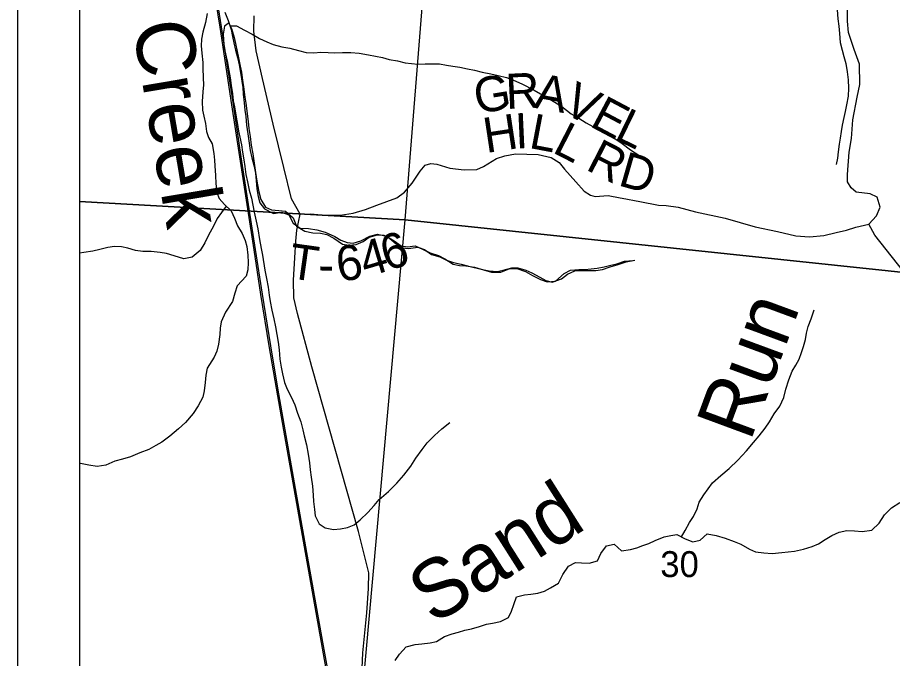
# Model space of a CAD drawing. Extents: x 0 to 40.8, y 0 to 22.
# Drawn here: x 2 to 3.414, y 18.699 to 19.735 of the extents above; entities that cross this region are included whole.
import ezdxf

# ---------------------------------------------------------------- set-up
doc = ezdxf.new("R2010")
doc.units = 0
for name, color, linetype in [('Default', 7, 'Continuous'), ('GM_X_County_Road', 7, 'Continuous'), ('GM_X_Minor_River', 7, 'Continuous'), ('GM_X_Minor_River_Text', 7, 'Continuous'), ('GM_X_Rail_Line', 7, 'Continuous'), ('GM_X_Section', 7, 'Continuous'), ('GM_X_Section_Text', 7, 'Continuous'), ('GM_X_Township_Road', 7, 'Continuous'), ('GM_X_Township_Road_Text', 7, 'Continuous'), ('SH_Cut_Line', 7, 'Continuous'), ('SH_Data', 7, 'Continuous')]:
    doc.layers.add(name, color=color, linetype=linetype)

msp = doc.modelspace()

# ---------------------------------------------------------------- linework, layer by layer
at = {"layer": 'Default'}
msp.add_lwpolyline([(3.6829, 20.9), (2.1, 20.9), (2.1, 17.4153), (2.4594, 17.3966), (2.8463, 17.3693), (2.8484, 17.3691), (3.1244, 17.3534), (3.4481, 17.3334), (3.5638, 19.132), (3.5742, 19.2945), (3.575, 19.3064), (3.6386, 20.2396), (3.6672, 20.5588), (3.6703, 20.6733)], close=True, dxfattribs=at)
at = {"layer": 'GM_X_County_Road'}
for points in [[(2.1, 20.4303), (2.1, 19.4381), (2.6264, 19.4085), (2.7045, 20.3832)], [(2.1, 19.4381), (2.1, 18.4259), (2.5343, 18.3862), (2.6264, 19.4085)]]:
    msp.add_lwpolyline(points, close=True, dxfattribs=at)
for points in [[(3.4403, 19.3142), (3.3856, 19.3835), (3.3759, 19.4012), (3.3878, 19.415), (3.3937, 19.429), (3.389, 19.4448), (3.3777, 19.4501), (3.355, 19.4532), (3.347, 19.4598), (3.341, 19.4698), (3.341, 19.4818), (3.344, 19.5176), (3.3476, 19.5399), (3.3496, 19.5699), (3.357, 19.6065), (3.3613, 19.6269), (3.3605, 19.6598), (3.3517, 19.6838), (3.3429, 19.7111), (3.341, 19.7294), (3.3414, 19.7557)], [(2.5547, 18.6345), (2.5581, 18.7086), (2.5645, 18.7732), (2.5674, 18.8123), (2.5679, 18.8378), (2.5508, 18.9044), (2.4758, 19.1705), (2.4527, 19.2569), (2.4464, 19.2824), (2.4458, 19.3109), (2.4482, 19.3466), (2.4499, 19.374), (2.4511, 19.3918), (2.457, 19.4172), (2.443, 19.442), (2.4304, 19.4926), (2.4129, 19.5631), (2.3958, 19.6365), (2.3858, 19.6814), (2.3818, 19.713), (2.3826, 19.7381)]]:
    msp.add_lwpolyline(points, dxfattribs=at)
at = {"layer": 'GM_X_Minor_River'}
for points in [[(2.3063, 19.7416), (2.3038, 19.7272), (2.2993, 19.7118), (2.2972, 19.7004), (2.297, 19.6894), (2.2979, 19.6776), (2.2995, 19.6628), (2.2997, 19.6533), (2.3002, 19.6377), (2.3003, 19.6264), (2.2997, 19.6154), (2.2983, 19.5998), (2.2991, 19.5854), (2.3012, 19.5759), (2.304, 19.564), (2.3053, 19.5511), (2.3085, 19.5415), (2.3144, 19.5312), (2.3175, 19.5156), (2.3184, 19.5049), (2.319, 19.4954), (2.3199, 19.4798), (2.3204, 19.4669), (2.322, 19.4525), (2.3256, 19.4429), (2.3345, 19.4332), (2.3453, 19.4228), (2.3508, 19.4109), (2.3554, 19.3987), (2.3628, 19.386), (2.3679, 19.3749), (2.3704, 19.3653), (2.3724, 19.3513), (2.3729, 19.3391), (2.3723, 19.3277), (2.3694, 19.3175), (2.3551, 19.3015), (2.3511, 19.2898), (2.3474, 19.2762), (2.3361, 19.259), (2.3289, 19.2432), (2.3276, 19.233), (2.327, 19.2227), (2.3248, 19.2072), (2.322, 19.1959), (2.3176, 19.1861), (2.3067, 19.1688), (2.3045, 19.1571), (2.3032, 19.1454), (2.3014, 19.1321), (2.2993, 19.1219), (2.2918, 19.1076), (2.284, 19.0953), (2.2712, 19.0807), (2.2604, 19.0707), (2.2461, 19.0584), (2.2331, 19.0488), (2.2235, 19.0433), (2.212, 19.0371), (2.1978, 19.0317), (2.1826, 19.0252), (2.1696, 19.0212), (2.1574, 19.0184), (2.1429, 19.0119), (2.1288, 19.0095), (2.1152, 19.0117), (2.102, 19.0142), (2.1, 19.0143)], [(2.3352, 19.7441), (2.3406, 19.7303), (2.3453, 19.7158), (2.3473, 19.7048), (2.3498, 19.6945), (2.3522, 19.6826), (2.3554, 19.6704), (2.3582, 19.6586), (2.3609, 19.6434), (2.3626, 19.6323), (2.3639, 19.6224), (2.3649, 19.6114), (2.3665, 19.5973), (2.3674, 19.5856), (2.3687, 19.5753), (2.37, 19.5612), (2.372, 19.5475), (2.3736, 19.5357), (2.376, 19.5205), (2.3788, 19.5083), (2.3823, 19.4945), (2.3848, 19.4835), (2.3857, 19.4717), (2.3869, 19.4584), (2.389, 19.4458), (2.3918, 19.4359), (2.3992, 19.4263)], [(3.3245, 19.7477), (3.3257, 19.7329), (3.3274, 19.7215), (3.3283, 19.7097), (3.3291, 19.6949), (3.3323, 19.6827), (3.3355, 19.672), (3.3383, 19.6609), (3.3404, 19.6476), (3.3424, 19.6346), (3.3429, 19.621), (3.3423, 19.6084), (3.3397, 19.5941), (3.3372, 19.5835), (3.3351, 19.5737), (3.3326, 19.5612), (3.3309, 19.551), (3.3292, 19.5404), (3.3279, 19.5305), (3.3261, 19.5181), (3.3248, 19.5078), (3.3227, 19.4976)], [(2.3418, 19.7265), (2.3344, 19.7213), (2.3322, 19.7085), (2.3328, 19.699), (2.3341, 19.6864), (2.3372, 19.6719), (2.3393, 19.6624), (2.3417, 19.6494), (2.3438, 19.638), (2.3454, 19.6255), (2.3474, 19.6121), (2.3487, 19.6007), (2.3504, 19.5908), (2.3535, 19.5741), (2.3556, 19.5626), (2.3573, 19.5516), (2.359, 19.5421), (2.3618, 19.5295), (2.3638, 19.5177), (2.3655, 19.5055), (2.3675, 19.4945), (2.3692, 19.4815), (2.3716, 19.4697), (2.3744, 19.4564), (2.3779, 19.4434), (2.3804, 19.432), (2.3824, 19.4209), (2.3855, 19.406), (2.3883, 19.3935), (2.391, 19.3763), (2.3938, 19.3618), (2.3959, 19.3512), (2.3999, 19.3268), (2.4023, 19.3135), (2.4051, 19.2994), (2.4067, 19.2864), (2.4081, 19.2762), (2.4112, 19.2621), (2.414, 19.2483), (2.4171, 19.2354), (2.4192, 19.2228), (2.4212, 19.2106), (2.4229, 19.1981), (2.4241, 19.1829), (2.4261, 19.1703), (2.4282, 19.1596), (2.4317, 19.1455), (2.436, 19.1348), (2.443, 19.121), (2.4484, 19.1091), (2.4527, 19.0957), (2.4578, 19.0816), (2.4609, 19.0686), (2.463, 19.0591), (2.4669, 19.0446), (2.4697, 19.0294), (2.4717, 19.0153), (2.473, 19.0042), (2.4746, 18.9921), (2.4766, 18.978), (2.4779, 18.9635), (2.4784, 18.9529), (2.4797, 18.94), (2.481, 18.9297), (2.4876, 18.9167), (2.4973, 18.9104), (2.5105, 18.9079), (2.5219, 18.9091), (2.533, 18.9112), (2.544, 18.9152), (2.5537, 18.9233), (2.566, 18.9352), (2.5761, 18.9464), (2.5843, 18.9561), (2.5993, 18.9691), (2.6132, 18.9829), (2.6245, 18.9956), (2.6357, 19.0101), (2.6436, 19.0233), (2.6537, 19.0371), (2.6622, 19.0476), (2.6738, 19.0599), (2.6854, 19.0703), (2.6985, 19.0806)], [(2.3432, 19.7222), (2.346, 19.7173), (2.3499, 19.7028), (2.3524, 19.6933), (2.3548, 19.6803), (2.3573, 19.67), (2.36, 19.6567), (2.3617, 19.6468), (2.3638, 19.6342), (2.3658, 19.6194), (2.3674, 19.6064), (2.3687, 19.5969), (2.3727, 19.5672), (2.374, 19.5558), (2.3757, 19.5429), (2.3777, 19.5288), (2.3804, 19.5151), (2.3821, 19.5037), (2.3841, 19.4888), (2.3858, 19.4778), (2.3878, 19.4648), (2.3899, 19.4538), (2.393, 19.4412), (2.4008, 19.4285), (2.4105, 19.4245), (2.4223, 19.4235), (2.4332, 19.4222), (2.4452, 19.4117), (2.451, 19.3983), (2.4641, 19.3901), (2.4773, 19.3875), (2.4898, 19.3865), (2.5, 19.3848), (2.5109, 19.3785), (2.5251, 19.3687), (2.5353, 19.3674), (2.5475, 19.3683), (2.5586, 19.373), (2.5682, 19.3804), (2.5815, 19.384), (2.5918, 19.3837), (2.6015, 19.3782), (2.6119, 19.3693), (2.6221, 19.363), (2.6319, 19.3621), (2.6467, 19.3641), (2.6576, 19.3601), (2.6692, 19.3522), (2.6824, 19.3486), (2.693, 19.343), (2.7043, 19.3394), (2.7171, 19.3365), (2.7273, 19.334), (2.7514, 19.3282), (2.7624, 19.3261), (2.7753, 19.3247), (2.7848, 19.3268), (2.7989, 19.3307), (2.8087, 19.3305), (2.8212, 19.3268), (2.8313, 19.3225), (2.8441, 19.3154), (2.8538, 19.3103), (2.8637, 19.3078), (2.8789, 19.3128), (2.8885, 19.3206), (2.9008, 19.326), (2.9103, 19.3266), (2.9243, 19.3263), (2.9345, 19.3265), (2.9452, 19.3278), (2.9578, 19.3321), (2.9707, 19.336), (2.9837, 19.3403), (2.9974, 19.3431)], [(2.3434, 19.7217), (2.3537, 19.7217), (2.3669, 19.715), (2.3792, 19.7083), (2.3912, 19.7016), (2.4029, 19.6961), (2.413, 19.6917), (2.427, 19.688), (2.4402, 19.6858), (2.4542, 19.6818), (2.4666, 19.6785), (2.4791, 19.6782), (2.4902, 19.6795), (2.5019, 19.6786), (2.5121, 19.6783), (2.5254, 19.6788), (2.5387, 19.6786), (2.5519, 19.6776), (2.567, 19.675), (2.5897, 19.6707), (2.6006, 19.6675), (2.6139, 19.665), (2.6263, 19.6621), (2.6369, 19.6611), (2.6471, 19.6601), (2.6589, 19.6603), (2.6718, 19.6604), (2.682, 19.6602), (2.693, 19.6581), (2.7032, 19.6567), (2.7149, 19.655), (2.727, 19.6521), (2.7383, 19.65), (2.7508, 19.6467), (2.7647, 19.6441), (2.7768, 19.6416), (2.79, 19.6383), (2.8013, 19.6339), (2.8152, 19.628), (2.8348, 19.6177), (2.8453, 19.6118), (2.8576, 19.6047), (2.8685, 19.5984), (2.8794, 19.5914), (2.8947, 19.5797), (2.9071, 19.5726), (2.9187, 19.5652), (2.9296, 19.5593), (2.9431, 19.5522), (2.9547, 19.5463), (2.9644, 19.5404), (2.9772, 19.5318), (2.9906, 19.5216), (3.0041, 19.5126)], [(2.3372, 19.4306), (2.3297, 19.4204), (2.3227, 19.4103), (2.316, 19.3968), (2.3093, 19.3848), (2.3026, 19.3709), (2.2951, 19.3585), (2.282, 19.3477), (2.2687, 19.3453), (2.2533, 19.3502), (2.2408, 19.3539), (2.2303, 19.3556), (2.2159, 19.357), (2.2026, 19.3573), (2.1909, 19.3586), (2.1781, 19.3623), (2.1679, 19.3648), (2.1565, 19.365), (2.1459, 19.3637), (2.1333, 19.3605), (2.1219, 19.3577), (2.1074, 19.3553), (2.1, 19.3546)], [(2.3992, 19.4263), (2.4135, 19.4184), (2.4264, 19.4208), (2.4384, 19.4164), (2.4454, 19.403), (2.457, 19.3948), (2.4702, 19.3941), (2.4835, 19.3923), (2.4974, 19.3886), (2.5125, 19.3811), (2.5222, 19.3756), (2.5327, 19.3716), (2.5426, 19.3707), (2.5548, 19.3742), (2.5693, 19.3819), (2.5819, 19.3851), (2.5963, 19.3821), (2.6086, 19.3743), (2.6202, 19.3661), (2.6301, 19.3644), (2.6426, 19.366), (2.6546, 19.3609), (2.6666, 19.3549), (2.6802, 19.3505), (2.6903, 19.3454), (2.7038, 19.3367), (2.714, 19.3343), (2.7242, 19.3337), (2.7382, 19.3319), (2.7529, 19.3274), (2.7661, 19.3238), (2.7809, 19.3235), (2.7943, 19.3289), (2.8068, 19.3298), (2.8208, 19.3246), (2.832, 19.3183), (2.8451, 19.3116), (2.8557, 19.3079), (2.8694, 19.3092), (2.8836, 19.3214), (2.8936, 19.3269), (2.9069, 19.3278), (2.9167, 19.328), (2.927, 19.3289), (2.9369, 19.3303), (2.9479, 19.3323), (2.959, 19.3351), (2.9685, 19.3372), (2.9807, 19.3415), (2.9944, 19.3424)], [(3.0727, 18.8958), (3.0789, 18.9061), (3.0859, 18.9189), (3.0922, 18.929), (3.0981, 18.9414), (3.1017, 18.952), (3.1088, 18.964), (3.1158, 18.9737), (3.1232, 18.9834), (3.1367, 18.9953), (3.1498, 19.0065), (3.1637, 19.0198), (3.178, 19.0347), (3.1893, 19.0482), (3.1986, 19.059), (3.2083, 19.0713), (3.2149, 19.0818), (3.2228, 19.0946), (3.2317, 19.1069), (3.2381, 19.1209), (3.2414, 19.1348), (3.2466, 19.1499), (3.2518, 19.1635), (3.2577, 19.1732), (3.2632, 19.183), (3.2668, 19.1936), (3.27, 19.2037), (3.2732, 19.2151), (3.275, 19.2253), (3.2778, 19.2358), (3.2822, 19.2483), (3.2874, 19.2626)], [(2.8904, 18.8484), (2.9015, 18.8542), (2.9114, 18.854), (2.9239, 18.8534), (2.9372, 18.8569), (2.9428, 18.869), (2.9517, 18.8813), (2.9639, 18.8841), (2.9758, 18.8732), (2.9907, 18.8756), (3.001, 18.8784), (3.0105, 18.8817), (3.0204, 18.8853), (3.0304, 18.89), (3.0449, 18.8958), (3.0556, 18.8982), (3.0655, 18.8996), (3.079, 18.8925), (3.091, 18.8877), (3.1032, 18.8908), (3.1144, 18.9009), (3.1287, 18.8983), (3.1435, 18.8938), (3.1578, 18.8886), (3.1687, 18.8839), (3.1829, 18.876), (3.1927, 18.8716), (3.2059, 18.8698), (3.2192, 18.8692), (3.2351, 18.8704), (3.2454, 18.8717), (3.2553, 18.8727), (3.2701, 18.8758), (3.2842, 18.8804), (3.2942, 18.8848), (3.3053, 18.8914), (3.316, 18.898), (3.3275, 18.9035), (3.3401, 18.9059), (3.3526, 18.9057), (3.3651, 18.9047), (3.3807, 18.9066), (3.3926, 18.9182), (3.4012, 18.9317), (3.4125, 18.9428), (3.4259, 18.9513)], [(2.61, 18.696), (2.617, 18.7065), (2.6282, 18.718), (2.6427, 18.7219), (2.6533, 18.7232), (2.667, 18.7245), (2.6769, 18.7266), (2.6899, 18.7346), (2.7025, 18.739), (2.7125, 18.7418), (2.7231, 18.745), (2.7338, 18.7471), (2.7468, 18.751), (2.7578, 18.7546), (2.7677, 18.7563), (2.7803, 18.7591), (2.7933, 18.7656), (2.7984, 18.7758), (2.802, 18.7867), (2.8065, 18.7992), (2.819, 18.8023), (2.8293, 18.8033), (2.8407, 18.8049), (2.8514, 18.8081), (2.8613, 18.8133), (2.8744, 18.8213), (2.8811, 18.8349), (2.8904, 18.8484)]]:
    msp.add_lwpolyline(points, dxfattribs=at)
at = {"layer": 'GM_X_Rail_Line'}
for points in [[(2.513, 18.6034), (2.4911, 18.7253), (2.4637, 18.8795), (2.4436, 18.9921), (2.4302, 19.0682), (2.4185, 19.136), (2.4069, 19.2045), (2.3933, 19.2876), (2.3823, 19.3597), (2.3722, 19.4258), (2.3592, 19.51), (2.3464, 19.5941), (2.3273, 19.7197), (2.3094, 19.8333), (2.2974, 19.9049), (2.2843, 19.9833), (2.2581, 20.1363), (2.2331, 20.2846), (2.2093, 20.4264), (2.1948, 20.5107), (2.1908, 20.5348)], [(2.5154, 18.6038), (2.4935, 18.7257), (2.4661, 18.8799), (2.446, 18.9926), (2.4326, 19.0686), (2.4208, 19.1364), (2.4093, 19.2049), (2.3957, 19.2879), (2.3846, 19.3601), (2.3746, 19.4262), (2.3616, 19.5103), (2.3488, 19.5945), (2.3297, 19.7201), (2.3118, 19.8337), (2.2998, 19.9053), (2.2866, 19.9837), (2.2605, 20.1367), (2.2355, 20.285), (2.2117, 20.4268), (2.1972, 20.5111), (2.1932, 20.5352)]]:
    msp.add_lwpolyline(points, dxfattribs=at)
at = {"layer": 'GM_X_Section'}
for points in [[(2.7045, 20.3832), (3.6475, 20.2502), (3.5805, 19.3077), (2.6264, 19.4085)], [(2.6264, 19.4085), (3.5805, 19.3077), (3.54, 18.3719), (2.5343, 18.3862)]]:
    msp.add_lwpolyline(points, close=True, dxfattribs=at)
at = {"layer": 'GM_X_Township_Road'}
for points in [[(2.457, 19.4172), (2.4727, 19.418), (2.498, 19.416), (2.5214, 19.416), (2.5424, 19.4188), (2.5622, 19.4249), (2.5807, 19.432), (2.5969, 19.4379), (2.613, 19.444), (2.6256, 19.4532), (2.6375, 19.4677), (2.6505, 19.4871), (2.6587, 19.4965), (2.6678, 19.4994), (2.6775, 19.4983), (2.6985, 19.4917), (2.7217, 19.4891), (2.7421, 19.4896), (2.753, 19.4945), (2.7739, 19.5073), (2.7872, 19.5116), (2.8046, 19.5149), (2.8411, 19.5141), (2.8625, 19.509), (2.875, 19.5009), (2.8839, 19.4902), (2.9023, 19.4695), (2.9156, 19.4545), (2.9257, 19.4481), (2.9337, 19.4458), (2.9545, 19.4476), (2.9741, 19.444), (2.9769, 19.4434)], [(2.9769, 19.4434), (3.0058, 19.4377), (3.0356, 19.4318), (3.0484, 19.4315), (3.0678, 19.4289), (3.0958, 19.421), (3.1433, 19.4108), (3.1918, 19.3971), (3.2282, 19.3895), (3.2576, 19.3826), (3.2799, 19.381), (3.3029, 19.3831), (3.3228, 19.3876), (3.3394, 19.3917), (3.3545, 19.3965), (3.3759, 19.4012)]]:
    msp.add_lwpolyline(points, dxfattribs=at)
at = {"layer": 'SH_Cut_Line'}
msp.add_lwpolyline([(7.7204, 20.9), (2.1, 20.9), (2.1, 17.4153), (2.4594, 17.3966), (2.8463, 17.3693), (2.8484, 17.3691), (3.1244, 17.3534), (3.4481, 17.3334), (4.5348, 17.2687), (4.8294, 17.2493), (5.3407, 17.2146), (5.6278, 17.197), (6.1785, 17.166), (6.9172, 17.1197), (7.4495, 17.0841), (7.4798, 17.5479), (7.4963, 17.9476), (7.5246, 18.2047), (7.5789, 18.8336), (7.595, 19.0259), (7.6007, 19.1025), (7.6007, 19.1071), (7.6192, 19.376), (7.7055, 20.511)], close=True, dxfattribs=at)
at = {"layer": 'SH_Data'}
for p, q in [((2, 21), (2, 14)), ((2.1, 20.9), (2.1, 14.1))]:
    msp.add_line(p, q, dxfattribs=at)

# ---------------------------------------------------------------- texts
at = {"layer": 'GM_X_Minor_River_Text'}
for s, height, rotation, p in [('Creek', 0.09471, 279.605, (2.1856, 19.724)), ('Run', 0.09471, 69.7075, (3.184, 19.0485)), ('Sand', 0.0947, 32.382, (2.672, 18.7524))]:
    msp.add_text(s, height=height, rotation=rotation, dxfattribs=at).set_placement(p)
at = {"layer": 'GM_X_Section_Text'}
msp.add_text('30', height=0.04186, rotation=0, dxfattribs=at).set_placement((3.0387, 18.8309))
at = {"layer": 'GM_X_Township_Road_Text'}
for s, rotation, p in [('G', 9.2264, (2.7423, 19.5794)), ('R', 2.6355, (2.7899, 19.5873)), ('A', 349.8717, (2.8332, 19.5896)), ('V', 333.9302, (2.8785, 19.5821)), ('E', 332.1085, (2.9229, 19.5604)), ('L', 334.0579, (2.9624, 19.5395)), ('H', 8.6035, (2.7571, 19.5161)), ('I', 2.6082, (2.805, 19.5235)), ('L', 349.2624, (2.8248, 19.5248)), ('L', 332.7948, (2.8625, 19.5182)), ('R', 332.7911, (2.9163, 19.4903)), ('D', 343.9482, (2.9688, 19.4646)), ('6', 17.3129, (2.5969, 19.3251)), ('T', 351.9554, (2.4362, 19.3144)), ('4', 16.4759, (2.5625, 19.3149)), ('6', 8.2446, (2.5191, 19.308)), ('-', 358.8646, (2.4857, 19.3078))]:
    msp.add_text(s, height=0.0568, rotation=rotation, dxfattribs=at).set_placement(p)

doc.saveas('drawing.dxf')
